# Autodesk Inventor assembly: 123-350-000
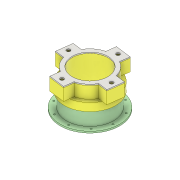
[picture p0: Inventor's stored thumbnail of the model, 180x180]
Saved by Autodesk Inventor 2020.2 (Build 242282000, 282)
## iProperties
Manager: www.cadconsulting.pl
Company: Fabian Stasiak CAD Consulting
Created: 2006-08
Part Number: 123-350-000
Document SubType Name: Assembly
Designer: F.Stasiak
Description: Głowica obrotowa
Author: F.Stasiak
Subject: Zbiór ćwiczeń. Autodesk Inventor 2020. Kurs podstawowy
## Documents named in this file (4)
- C:\2020_Kurs_podstawowy\R6 Zespoły\BOM\123-350-000.iam
- C:\2020_Kurs_podstawowy\R6 Zespoły\BOM\123-400-005.ipt
- C:\2020_Kurs_podstawowy\R6 Zespoły\BOM\123-400-006.ipt
- C:\2020_Kurs_podstawowy\R6 Zespoły\BOM\123-400-008.ipt
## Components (3 placed, 3 different names)
1. 123-400-005:1
2. 123-400-006:1
3. 123-400-008:1
